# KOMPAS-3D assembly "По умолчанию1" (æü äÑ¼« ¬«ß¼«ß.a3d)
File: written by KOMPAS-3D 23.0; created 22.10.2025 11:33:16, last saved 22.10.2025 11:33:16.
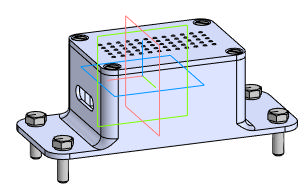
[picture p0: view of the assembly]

Document properties: Автор: ARM_513_VVK; Полное имя файла: F:\Демо\Демо вариант космос\СБ Демо космос.a3d

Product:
- Component [assembly]: 0  | qty 1  | Автор: ARM_513_VVK; source file: СБ Демо космос_1.a3d
- Component [detail]: Шайба 6Л ГОСТ 6402  | qty 4  | Автор: ARM_513_VVK; source file: Шайба 6Л ГОСТ 6402.m3d
- Component [detail]: Болт М6x20 ГОСТ 7805  | qty 4  | Автор: ARM_513_VVK; source file: Болт М6x20 ГОСТ 7805.m3d
- Component [detail]: Винт A.М4x16 ГОСТ 17475  | qty 4  | Автор: ARM_513_VVK; source file: Винт A.М4x16 ГОСТ 17475.m3d
- Component [detail]: Крышка-1  | qty 1  | Автор: ARM_513_VVK; source file: Крышка-1.m3d
- Component [detail]: Корпус-1  | qty 1  | Автор: ARM_513_VVK; source file: Корпус-1.m3d
- Part/product: По умолчанию1

Referenced files in F:\Демо\Демо вариант космос\: СБ Демо космос_1.a3d, Шайба 6Л ГОСТ 6402.m3d, Болт М6x20 ГОСТ 7805.m3d, Винт A.М4x16 ГОСТ 17475.m3d, Крышка-1.m3d, Корпус-1.m3d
